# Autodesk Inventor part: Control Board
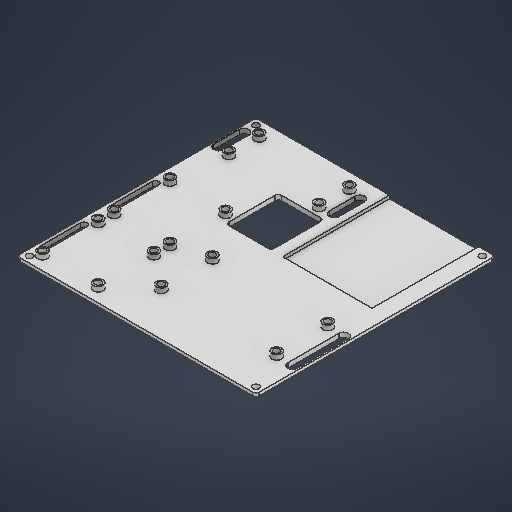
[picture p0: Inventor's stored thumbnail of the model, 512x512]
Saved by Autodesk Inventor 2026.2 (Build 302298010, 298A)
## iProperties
Created: 2026-04
Part Number: Control Board
Material: 일반
Document SubType Name: Modeling
Designer: work
Density: 1 g/cm^3
Appearance: 기본값
Author: work
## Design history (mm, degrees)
sketch "스케치1"
  geometry: L1 (150, -150)-(0, -150); L2 (0, -150)-(0, 0); L3 (0, 0)-(150, 0); L4 (150, 0)-(150, -150); L5 (150, -150)-(0, 0); L6 (0, -150)-(150, 0); L7 (4, -4)-(146, -4); L8 (146, -4)-(146, -146); L9 (146, -146)-(4, -146); L10 (4, -146)-(4, -4); L11 (4, -4)-(146, -146); L12 (146, -4)-(4, -146); L13 (14, -27)-(86.4, -27); L14 (10.2, -88)-(10.2, -78); L15 (7, -59)-(7, -27); L16 (4, -43)-(14, -43); L17 (4, -27)-(4, -59); L18 (14, -59)-(14, -27); L19 (50.2, -27)-(50.2, -59); L20 (10.2, -78)-(10.2, -8); L21 (90.2, -78)-(10.2, -78); L22 (86.4, -59)-(14, -59); L23 (86.4, -43)-(14, -43); L24 (90.2, -8)-(10.2, -78); L25 (10.2, -8)-(90.2, -8); L26 (10.2, -8)-(90.2, -78); L27 (86.4, -27)-(86.4, -59); L28 (90.2, -8)-(90.2, -78); L29 (1, -27)-(1, -59); L30 (107, -8)-(142, -8); L31 (107, -8)-(142, -43); L32 (142, -43)-(107, -43); L33 (142, -8)-(107, -43); L34 (142, -8)-(142, -43); L35 (107, -43)-(107, -8); L36 (107, -53)-(142, -53); L37 (107, -53)-(142, -88); L38 (142, -88)-(107, -88); L39 (142, -53)-(107, -88); L40 (142, -53)-(142, -88); L41 (107, -88)-(107, -53); L42 (109.7, -130.5)-(146, -130.5); L43 (138, -121)-(138, -140); L44 (138, -140)-(81.4, -140); L45 (81.4, -140)-(81.4, -121); L46 (138, -140)-(81.4, -121); L47 (81.4, -121)-(138, -121); L48 (81.4, -140)-(138, -121); L49 (146, -138.5)-(146, -122.5); L50 (143, -138.5)-(143, -122.5); L51 (109.7, -121)-(109.7, -140); L52 (109.7, -130.5)-(73.4, -130.5); L53 (76.4, -138.5)-(76.4, -122.5); L54 (73.4, -138.5)-(73.4, -122.5); L55 (70.4, -122.5)-(70.4, -138.5); L56 (149, -122.5)-(149, -138.5); L57 (66.2, -83)-(10.2, -83); L58 (10.2, -83)-(10.2, -166); L59 (10.2, -166)-(66.2, -166); L60 (66.2, -166)-(66.2, -83); L61 (102, -83)-(73.4, -83); L62 (73.4, -83)-(73.4, -116); L63 (73.4, -116)-(102, -116); L64 (102, -116)-(102, -83)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; C1 r 2 at (146, -4); C2 r 2 at (146, -146); C3 r 2 at (4, -4); C4 r 2 at (4, -146); C5 r 2 at (86.4, -59); C6 r 2 at (14, -59); C7 r 2 at (86.4, -27); C8 r 2 at (14, -27); C9 r 2 at (142, -8); C10 r 2 at (142, -43); C11 r 2 at (107, -8); C12 r 2 at (107, -43); C13 r 2 at (142, -53); C14 r 2 at (142, -88); C15 r 2 at (107, -53); C16 r 2 at (107, -88); C17 r 2 at (138, -140); C18 r 2 at (138, -121); C19 r 2 at (81.4, -121); C20 r 2 at (81.4, -140); A1 r 3 centre (4, -59) between (1, -59) and (7, -59); A2 r 3 centre (4, -27) between (7, -27) and (1, -27); A3 r 3 centre (146, -138.5) between (143, -138.5) and (149, -138.5); A4 r 3 centre (146, -122.5) between (149, -122.5) and (143, -122.5); A5 r 3 centre (73.4, -138.5) between (70.4, -138.5) and (76.4, -138.5); A6 r 3 centre (73.4, -122.5) between (76.4, -122.5) and (70.4, -122.5); A7 r 2 centre (146, -13) between (148, -13) and (144, -13); A8 r 2 centre (146, -38) between (144, -38) and (148, -38); A9 r 2 centre (146, -83) between (144, -83) and (148, -83); A10 r 2 centre (146, -58) between (148, -58) and (144, -58); 10 further points
  constraints: 148 end point, 30 centre point, 25 midpoint, 22 parallel, 21 coincident, 20 point on circle, 16 tangent, 11 perpendicular, 9 horizontal, 7 point on line, 7 symmetric about line, 5 collinear, 3 vertical, 2 other
  dimensions: "d0" = 150 distance of L2.end L3.end; "d1" = 150 distance of L1.end L2.end; "d2" = 4 distance between parallel lines of L4 L8; "d3" = 4 diameter of C1; "d4" = 4 diameter of C2; "d5" = 4 diameter of C3; "d6" = 4 diameter of C4; "d10" = 72.4 distance of L13.start L13.end; "d11" = 32 distance of L18.start L13.start; "d12" = 80 distance of L21.start L14.end; "d13" = 70 distance of L24.start L21.start; "d14" = 4 diameter of C8; "d15" = 4 diameter of C6; "d16" = 4 diameter of C7; "d17" = 4 diameter of C5; "d18" = 6 diameter of A1; "d19" = 10 distance from line of L13.start L17; "d20" = 32 distance of L17.start L17.end; "d21" = 4 vertical distance of L7.start L20.end; "d22" = 35 distance of L31.end L32.end; "d23" = 35 distance of L30.end L31.end; "d24" = 4 diameter of C9; "d25" = 4 diameter of C10; "d26" = 4 diameter of C11; "d27" = 4 diameter of C12; "d28" = 35 distance of L37.end L38.end; "d29" = 35 distance of L36.end L37.end; "d30" = 4 diameter of C13; "d31" = 4 diameter of C14; "d32" = 4 diameter of C15; "d33" = 4 diameter of C16; "d34" = 10 distance of C13.centre L31.end; "d37" = 56.6 distance of L45.end L43.start; "d38" = 19 distance of L44.end L45.end; "d39" = 4 diameter of C19; "d40" = 4 diameter of C20; "d41" = 4 diameter of C18; "d42" = 4 diameter of C17; "d43" = 16 distance of L54.start L54.end; "d44" = 8 distance between parallel lines of L45 L54; "d45" = 3 radius of A5; "d46" = 6 vertical distance of L8.end L43.end; "d47" = 56 distance of L59.end L58.end; "d48" = 83 distance of L58.end L57.end; "d49" = 5 distance between parallel lines of L21 L57; "d50" = 5 distance between parallel lines of L47 L63; "d51" = 5 distance between parallel lines of L41 L64; "d52" = 25 distance of L67.start L67.end; "d53" = 2 radius of A8; "d54" = 25 distance of L69.start L69.end; "d55" = 2 radius of A9
extrude "돌출1" new body sketch "스케치1" distance "d56" = 3; taper "d57" = 0 deg
extrude "돌출2" join sketch "스케치1" distance "d58" = 1; taper "d59" = 0 deg
sketch "스케치2"
  geometry: L1 (-150, 0)-(0, 0) reference; L2 (0, 0)-(0, 150) reference; L3 (0, 150)-(-10.2, 150) reference; L4 (-10.2, 150)-(-10.2, 83) reference; L5 (-10.2, 83)-(-66.2, 83) reference; L6 (-66.2, 83)-(-66.2, 150) reference; L7 (-66.2, 150)-(-150, 150) reference; L8 (-150, 150)-(-150, 0) reference; L9 (-148, 58)-(-148, 83) reference; L10 (-144, 83)-(-144, 58) reference; L11 (-148, 13)-(-148, 38) reference; L12 (-144, 38)-(-144, 13) reference; L13 (-102, 83)-(-102, 116) reference; L14 (-102, 116)-(-73.4, 116) reference; L15 (-73.4, 116)-(-73.4, 83) reference; L16 (-73.4, 83)-(-102, 83) reference; L17 (-70.4, 138.5)-(-70.4, 122.5) reference; L18 (-76.4, 122.5)-(-76.4, 138.5) reference; L19 (-149, 122.5)-(-149, 138.5) reference; L20 (-143, 138.5)-(-143, 122.5) reference; L21 (-1, 59)-(-1, 27) reference; L22 (-7, 27)-(-7, 59) reference; C1 r 2 at (-81.4, 140) reference; C2 r 2 at (-138, 121) reference; C3 r 2 at (-107, 88) reference; C4 r 2 at (-142, 88) reference; C5 r 2 at (-107, 43) reference; C6 r 2 at (-142, 43) reference; C7 r 2 at (-146, 146) reference; C8 r 2 at (-4, 4) reference; C9 r 2 at (-4, 146) reference; C10 r 2 at (-86.4, 59) reference; C11 r 2 at (-14, 59) reference; C12 r 2 at (-86.4, 27) reference; C13 r 2 at (-14, 27) reference; C14 r 2 at (-107, 8) reference; C15 r 2 at (-142, 53) reference; C16 r 2 at (-107, 53) reference; C17 r 2 at (-138, 140) reference; C18 r 2 at (-81.4, 121) reference; C19 r 2 at (-142, 8) reference; C20 r 2 at (-146, 4) reference; C21 r 3 at (-142, 8); C22 r 3 at (-142, 43); C23 r 3 at (-142, 53); C24 r 3 at (-142, 88); C25 r 2 at (-142, 8); C26 r 2 at (-142, 43); C27 r 2 at (-142, 53); C28 r 2 at (-142, 88); C29 r 2 at (-107, 88); C30 r 3 at (-107, 88); C31 r 2 at (-107, 53); C32 r 3 at (-107, 53); C33 r 2 at (-107, 43); C34 r 3 at (-107, 43); C35 r 2 at (-107, 8); C36 r 3 at (-107, 8); C37 r 2 at (-86.4, 27); C38 r 3 at (-86.4, 27); C39 r 2 at (-86.4, 59); C40 r 3 at (-86.4, 59); C41 r 2 at (-14, 27); C42 r 3 at (-14, 27); C43 r 2 at (-14, 59); C44 r 3 at (-14, 59); C45 r 2 at (-81.4, 121); C46 r 3 at (-81.4, 121); C47 r 2 at (-81.4, 140); C48 r 3 at (-81.4, 140); C49 r 2 at (-138, 121); C50 r 3 at (-138, 121); C51 r 2 at (-138, 140); C52 r 3 at (-138, 140); A1 r 2 centre (-146, 58) between (-148, 58) and (-144, 58) reference; A2 r 2 centre (-146, 83) between (-144, 83) and (-148, 83) reference; A3 r 2 centre (-146, 13) between (-148, 13) and (-144, 13) reference; A4 r 2 centre (-146, 38) between (-144, 38) and (-148, 38) reference; A5 r 3 centre (-73.4, 138.5) between (-70.4, 138.5) and (-76.4, 138.5) reference; A6 r 3 centre (-73.4, 122.5) between (-76.4, 122.5) and (-70.4, 122.5) reference; A7 r 3 centre (-146, 138.5) between (-143, 138.5) and (-149, 138.5) reference; A8 r 3 centre (-146, 122.5) between (-149, 122.5) and (-143, 122.5) reference; A9 r 3 centre (-4, 59) between (-1, 59) and (-7, 59) reference; A10 r 3 centre (-4, 27) between (-7, 27) and (-1, 27) reference; 1 further point
  constraints: 32 centre point, 20 coincident
  dimensions: "d60" = 6 diameter of C21; "d61" = 6 diameter of C22; "d62" = 6 diameter of C23; "d63" = 6 diameter of C24; "d64" = 4 diameter of C25; "d65" = 4 diameter of C26; "d66" = 4 diameter of C27; "d67" = 4 diameter of C28; "d68" = 6 diameter of C30; "d69" = 4 diameter of C29; "d70" = 6 diameter of C32; "d71" = 4 diameter of C31; "d72" = 6 diameter of C34; "d73" = 4 diameter of C33; "d74" = 6 diameter of C36; "d75" = 4 diameter of C35; "d76" = 6 diameter of C38; "d77" = 4 diameter of C37; "d78" = 6 diameter of C40; "d79" = 4 diameter of C39; "d80" = 6 diameter of C42; "d81" = 4 diameter of C41; "d82" = 6 diameter of C44; "d83" = 4 diameter of C43; "d84" = 6 diameter of C46; "d85" = 4 diameter of C45; "d86" = 6 diameter of C48; "d87" = 4 diameter of C47; "d88" = 6 diameter of C50; "d89" = 4 diameter of C49; "d90" = 6 diameter of C52; "d91" = 4 diameter of C51
extrude "돌출3" join sketch "스케치2" distance "d92" = 3; taper "d93" = 0 deg
fillet "모깎기1" dims "d94" = 2
chamfer "모따기1" distance "d95" = 1; stored, may be unused: second distance "d96" = 2, angle "d97" = 45 deg
node "솔리드1"
node "투영된 루프1"
